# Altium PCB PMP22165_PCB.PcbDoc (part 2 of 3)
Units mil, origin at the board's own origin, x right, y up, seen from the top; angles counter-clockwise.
Board outline 3700 x 3000 mil, 4 copper layers (Top Layer, Signal Layer 1, Signal Layer 2, Bottom Layer), stack 61.634 mil thick; 232 components, 104 nets, 594 pads, 232 vias.
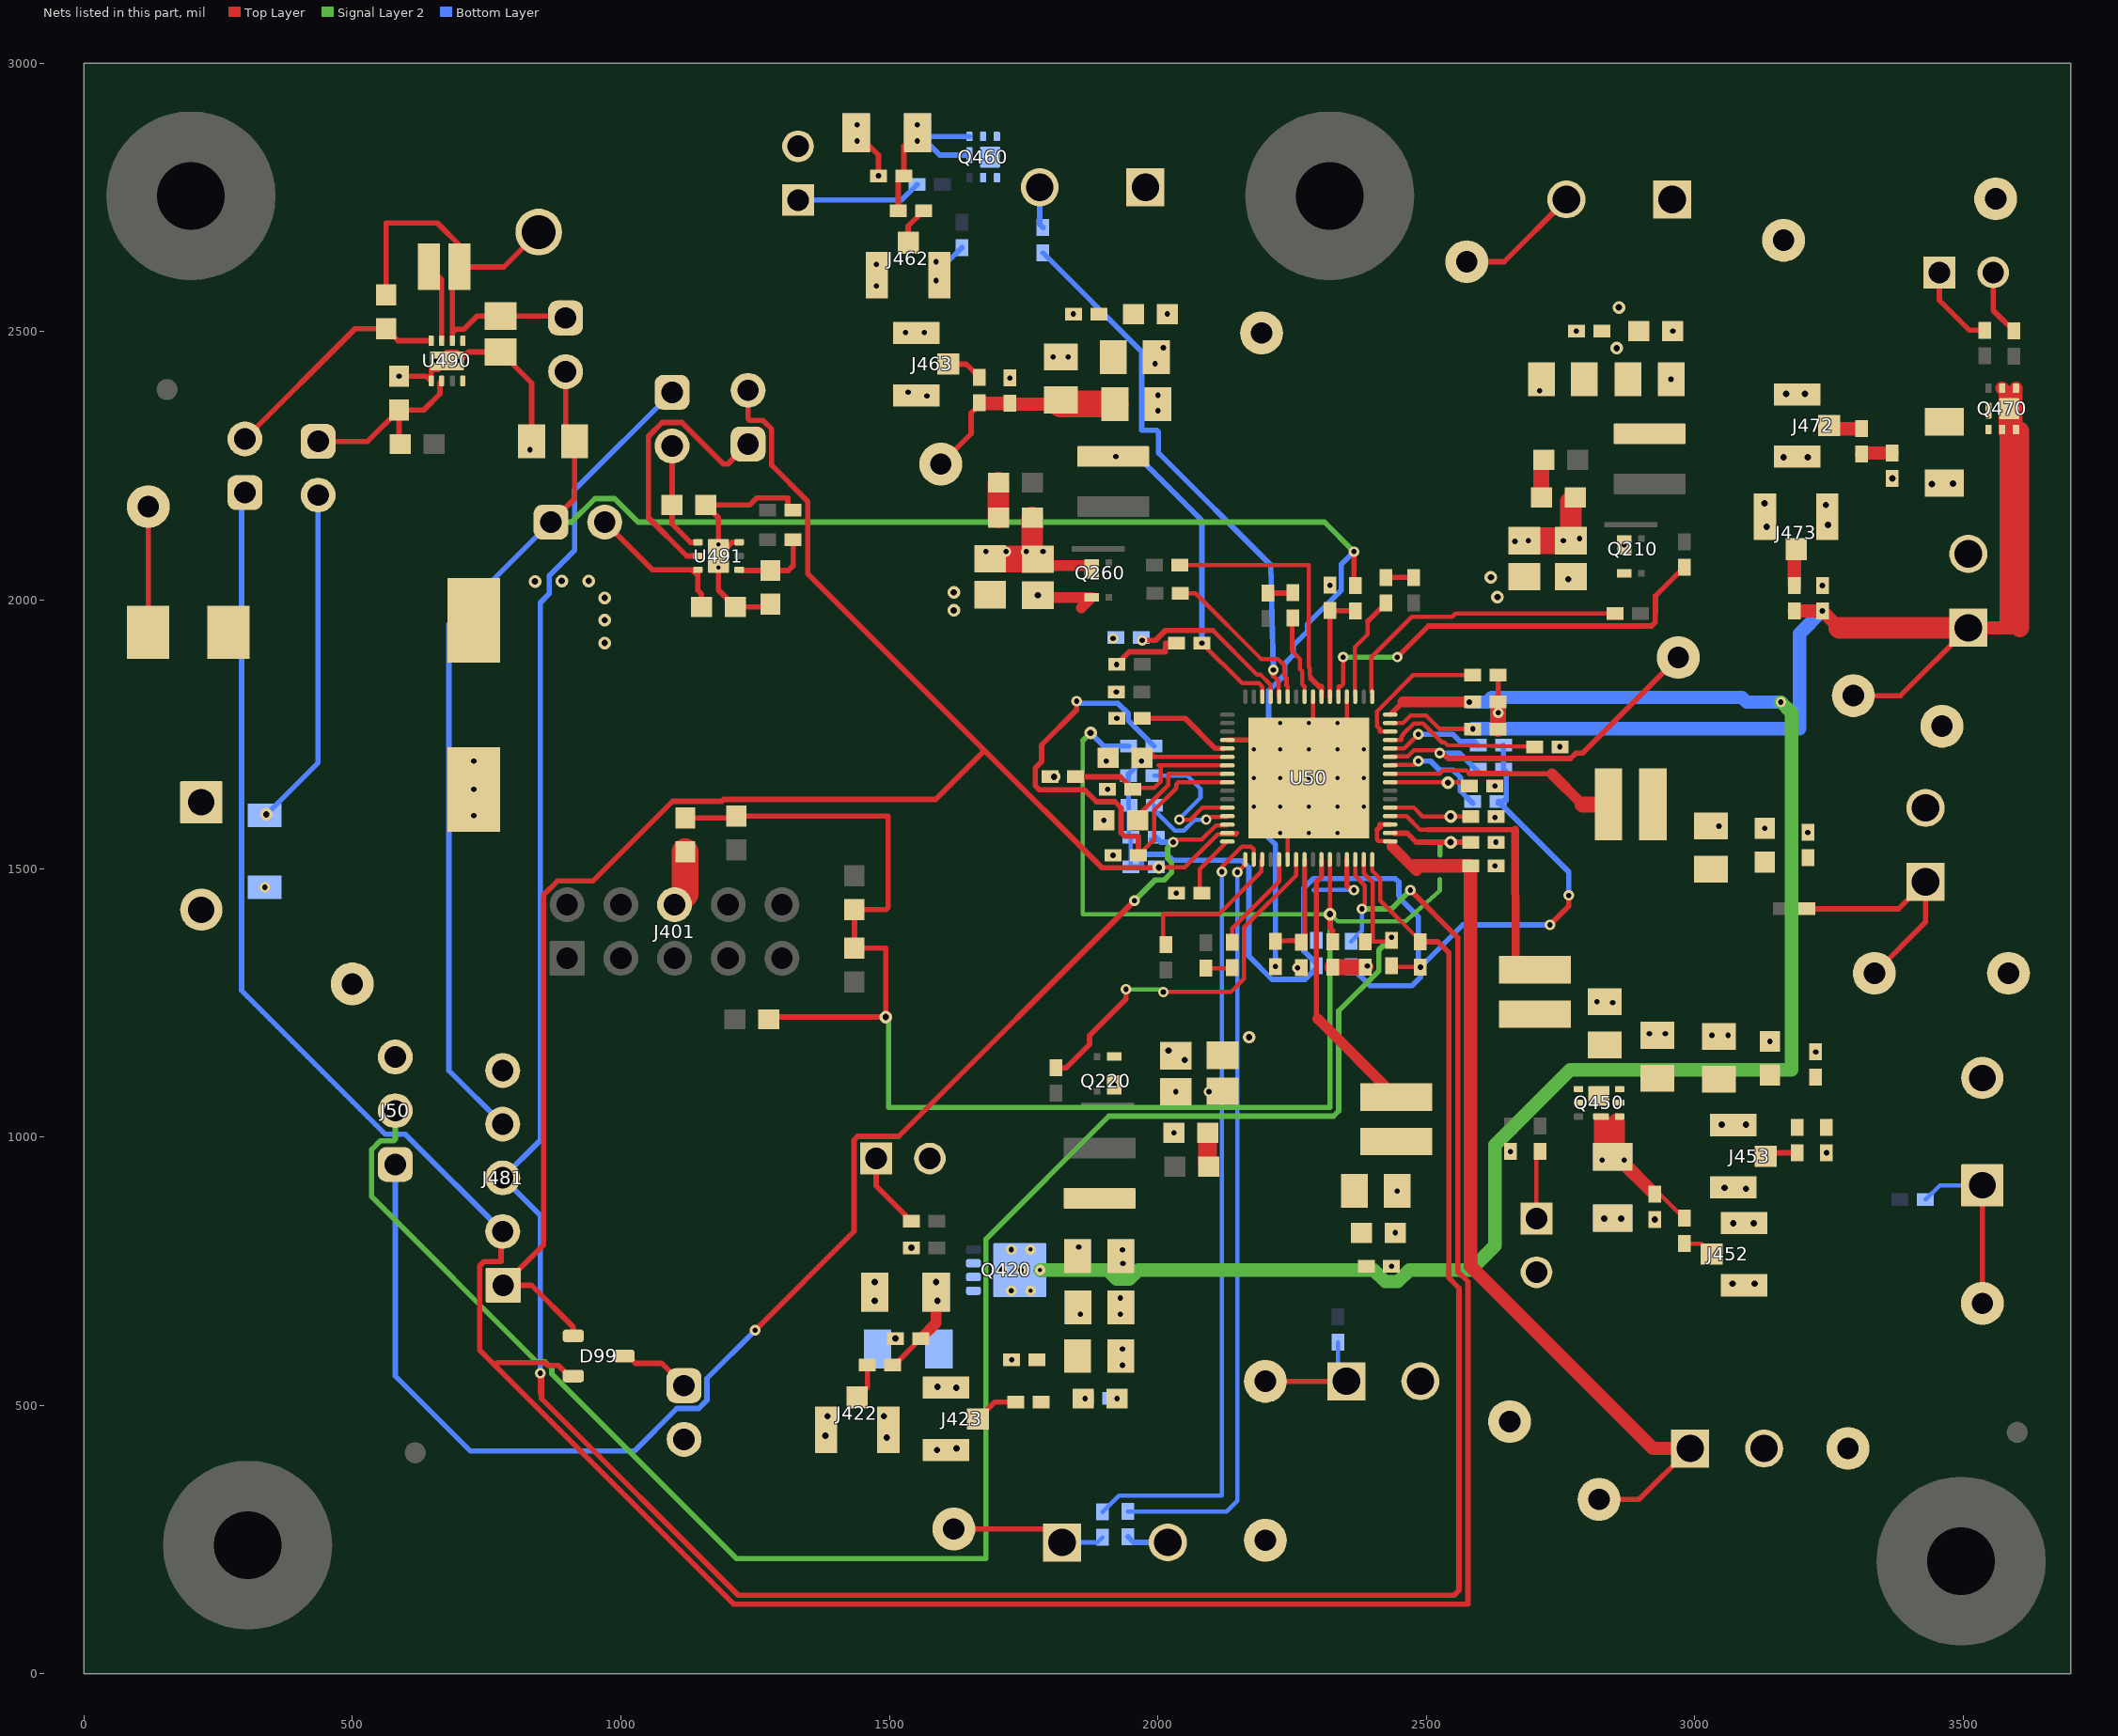
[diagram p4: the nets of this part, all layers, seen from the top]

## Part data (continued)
H5 H6 H7 H8: library part CMP-0003610-1, "Standoff, Hex, 0.5\"L #4-40 Nylon", Manufacturer=Keystone, Supplier Part Number 1=36-1902C-ND
J50: library part CMP-0075407-2, "Header, 100mil, 3x1, Gold, TH", Color=Black, Current_A=6.3A, Manufacturer=Samtec, Supplier Part Number 1=SAM1029-03-ND, Voltage_V=550V
J99 J491 J492 J493 J494 J495 J496: library part CMP-0075405-3, "Header, 100mil, 2x1, Gold, TH", Color=Black, Current_A=6.3A, Manufacturer=Samtec, Supplier Part Number 1=SAM1029-02-ND, Voltage_V=550V
J211 J221 J430 J440: library part CMP-0054825-2, "Terminal Block, 3.5mm, 2x1, Tin, TH", Color=Green, Current_A=10A, Manufacturer="Wurth Elektronik", Supplier Part Number 1=732-2747-ND, Voltage_V=300V
J400 J450: library part CMP-0074910-1, "Terminal Block, 5.08 mm, 2x1, Brass, TH", Color=Blue, Current_A=15A, Manufacturer="On-Shore Technology", Supplier Part Number 1=ED1609-ND, Voltage_V=300V
J401: library part CMP-0075410-2, "Header, 100mil, 5x2, Gold, TH", Color=Black, Current_A=6.3A, Manufacturer=Samtec, Supplier Part Number 1=SAM1028-05-ND, Voltage_V=550V
J410 J420 J460: library part CMP-0055506-1, "Terminal Block, 2x1, 5mm, Green, TH", Color=Green, Manufacturer="Phoenix Contact", PartNumber=1935776, Supplier Part Number 1=277-6405-ND
J421: library part CMP-0054947-1, "Header, 100mil, 2x1, Gold, TH", Manufacturer="TE Connectivity"
J422 J423 J452 J453 J462 J463 J472 J473: library part CMP-0075320-1, "Receptacle, Ultra Miniature Coaxial, Male Pin, 50 ohm, SMT", Color=Beige, Manufacturer="Hirose Electric Co. Ltd.", Supplier Part Number 1=H122041-ND
J451 J461 J471: library part CMP-0054947-1, "Header, 100mil, 2x1, Gold, TH", Manufacturer="TE Connectivity", PartNumber=5-146261-1
J481: library part CMP-0075411-1, "Header, 100mil, 5x1, Gold, TH", Color=Black, Current_A=6.3A, Manufacturer=Samtec, Supplier Part Number 1=SAM1029-05-ND, Voltage_V=550V
L210 L220 L260: library part CMP-0060983-2, "Inductor, Shielded, Composite, 1 µH, 8.75 A, 0.01 ohm, AEC-Q200 Grade 1, SMD", Manufacturer=Coilcraft, Value1="0.01 ohm", Value2=8.75A, ValueDisplayed=1uH
L230 L240 L250: library part CMP-0064156-1, "Inductor, Wirewound, 470 nH, 4.8 A, 0.018 ohm, SMD", Manufacturer="Wurth Elektronik", Supplier Part Number 1=732-5691-1-ND, Value1="0.018 ohm", Value2=4.8A, ValueDisplayed=470nH
L400: library part CMP-0059700-1, "Inductor, 55 nH, 30 A, 0.0002 ohm, SMD", Manufacturer="Delta Electronics Inc.", Value1="0.0002 ohm", Value2=30A, ValueDisplayed=55nH
L410: library part CMP-0061170-1, "Inductor, Shielded, Composite, 2.2 uH, 1.3 A, 0.16 ohm, SMD", Manufacturer=Coilcraft, Value1="0.16 ohm", Value2=1.3A, ValueDisplayed=2.2uH
LBL1: library part CMP-0003625-1, "Thermal Transfer Printable Labels, 0.650\" W x 0.200\" H - 10,000 per roll", Manufacturer=Brady, Supplier Part Number 1=97C5133
Logo1: library part CMP-0074838-1, "Texas Instrument Corporate Signature"
Logo2: library part CMP-0074844-1
Logo4: library part CMP-0074769-1
Q210 Q220 Q260: library part CMP-0066162-1, "Synchronous Buck NexFET Power Block II, MPC0005A (PTAB-5)", Alternate Manufacturer="Texas Instruments"
Q420: library part CMP-0000593-2, "MOSFET, N-CH, 30 V, 20 A, DNH0008A (VSONP-8)", Alternate Manufacturer=None, Manufacturer="Texas Instruments", PartNumber=CSD17579Q3A, Supplier Part Number 1=296-39998-1-ND, Value1=0.014, Value2="5.3 nC"
Q450 Q460 Q470: library part CMP-0000248-1, "MOSFET, N-CH, 25 V, 5 A, DQK0006C (WSON-6)", Alternate Manufacturer=None, Manufacturer="Texas Instruments", PartNumber=CSD16301Q2, Supplier Part Number 1=296-25260-1-ND, Value1=0.02, Value2="2 nC"
R50 R51 R52 R54 R55 R56 R210 R211 R212 R215 R220 R221 R222 R225 R226 R230 R240 R250 R260 R261 R262 R265: library part CMP-0026822-3, "RES, 0, 5%, 0.063 W, AEC-Q200 Grade 0, 0402", Manufacturer=Vishay-Dale, PartNumber=CRCW04020000Z0ED, Power_W=63mW, Supplier Part Number 1=541-0.0JCT-ND, TempCo="200 ppm/C", Tolerance_%=5%, Value2=0.063W, Value_Code=0000, ValueDisplayed=0
R57 R58 R59 R60 R61 R62 R63 R64 R65 R66 R67: library part CMP-0026823-3, "RES, 100 k, 5%, 0.063 W, AEC-Q200 Grade 0, 0402", Manufacturer=Vishay-Dale, PartNumber=CRCW0402100KJNED, Power_W=63mW, Supplier Part Number 1=541-100KJCT-ND, TempCo="200 ppm/C", Tolerance_%=5%, Value2=0.063W, Value_Code=100k
R213 R223 R263 R495: library part CMP-0025958-3, "RES, 10.0 k, 1%, 0.063 W, AEC-Q200 Grade 0, 0402", Manufacturer=Vishay-Dale, Power_W=63mW, Supplier Part Number 1=541-10.0KLCT-ND, TempCo="100 ppm/C", Tolerance_%=1%, Value2=0.063W, Value_Code=10k0, ValueDisplayed=10.0k
R214 R224 R264: library part CMP-0025834-4, "RES, 5.1, 5%, 0.1 W, AEC-Q200 Grade 0, 0603", Manufacturer=Vishay-Dale, PartNumber=CRCW06035R10JNEA, Power_W=100mW, Supplier Part Number 1=541-5.1GCT-ND, TempCo="200 ppm/C", Tolerance_%=5%, Value2=0.1W, Value_Code=5R10, ValueDisplayed=5.1
R401 R402 R403 R404: library part CMP-0025701-4, "RES, 10 k, 5%, 0.1 W, AEC-Q200 Grade 0, 0603", Manufacturer=Vishay-Dale, Power_W=100mW, Supplier Part Number 1=541-10KGCT-ND, TempCo="200 ppm/C", Tolerance_%=5%, Value2=0.1W, Value_Code=10k0, ValueDisplayed=10k
R421 R451 R461 R471: library part CMP-0026866-3, "RES, 1.0, 5%, 0.063 W, AEC-Q200 Grade 0, 0402", Manufacturer=Vishay-Dale, PartNumber=CRCW04021R00JNED, Power_W=63mW, Supplier Part Number 1=541-1.0JCT-ND, TempCo="200 ppm/C", Tolerance_%=5%, Value2=0.063W, Value_Code=1R00, ValueDisplayed=1.0
R422 R452 R462 R472: library part CMP-0025958-3, "RES, 10.0 k, 1%, 0.063 W, AEC-Q200 Grade 0, 0402", Manufacturer=Vishay-Dale, PartNumber=CRCW040210K0FKED, Power_W=63mW, Supplier Part Number 1=541-10.0KLCT-ND, TempCo="100 ppm/C", Tolerance_%=1%, Value2=0.063W, Value_Code=10k0, ValueDisplayed=10.0k
R423 R424 R429 R453 R454 R463 R464: library part CMP-0016745-3, "RES, 1.00, 1%, 0.25 W, AEC-Q200 Grade 0, 1206", Manufacturer=Vishay-Dale, PartNumber=CRCW12061R00FKEA, Power_W=250mW, Supplier Part Number 1=53K1855, TempCo="100 ppm/C", Tolerance_%=1%, Value2=0.25W, Value_Code=1R00, ValueDisplayed=1.00
R425 R426 R455 R456 R465 R466: library part CMP-0026404-2, "RES, 49.9, 1%, 0.063 W, AEC-Q200 Grade 0, 0402", Manufacturer=Vishay-Dale, PartNumber=CRCW040249R9FKED, Power_W=63mW, Supplier Part Number 1=541-49.9LCT-ND, TempCo="100 ppm/C", Tolerance_%=1%, Value2=0.063W, Value_Code=49R9, ValueDisplayed=49.9
R473: library part CMP-0016583-3, "RES, 10.0, 1%, 0.25 W, AEC-Q200 Grade 0, 1206", Manufacturer=Vishay-Dale, Power_W=250mW, Supplier Part Number 1=541-10.0FCT-ND, TempCo="100 ppm/C", Tolerance_%=1%, Value2=0.25W, Value_Code=10R0, ValueDisplayed=10.0
R475 R476: library part CMP-0026404-2, "RES, 49.9, 1%, 0.063 W, AEC-Q200 Grade 0, 0402", Manufacturer=Vishay-Dale, Power_W=63mW, Supplier Part Number 1=541-49.9LCT-ND, TempCo="100 ppm/C", Tolerance_%=1%, Value2=0.063W, Value_Code=49R9, ValueDisplayed=49.9
R490: library part CMP-0025697-4, "RES, 0, 5%, 0.1 W, AEC-Q200 Grade 0, 0603", Manufacturer=Vishay-Dale, Power_W=100mW, Supplier Part Number 1=541-0.0GCT-ND, TempCo="200 ppm/C", Tolerance_%=5%, Value2=0.1W, Value_Code=0000, ValueDisplayed=0
R491 R493: library part CMP-0021990-4, "RES, 100 k, 1%, 0.1 W, AEC-Q200 Grade 0, 0603", Manufacturer=Vishay-Dale, Power_W=100mW, Supplier Part Number 1=541-100KHCT-ND, TempCo="100 ppm/C", Tolerance_%=1%, Value2=0.1W, Value_Code=100k
R494: library part CMP-0026407-2, "RES, 4.22 k, 1%, 0.063 W, AEC-Q200 Grade 0, 0402", Manufacturer=Vishay-Dale, Power_W=63mW, Supplier Part Number 1=541-4.22KLCT-ND, TempCo="100 ppm/C", Tolerance_%=1%, Value2=0.063W, Value_Code=4k22, ValueDisplayed=4.22k
TP99: library part CMP-0055139-1, "Test Point, Miniature, White, TH", Color=White, Manufacturer=Keystone, Supplier Part Number 1=36-5002-ND
TP211 TP221 TP400 TP410 TP420 TP430 TP440 TP450 TP460: library part CMP-0055137-1, "Test Point, Miniature, Red, TH", Color=Red, Manufacturer=Keystone, Supplier Part Number 1=36-5000-ND
TP212 TP222 TP401 TP411 TP421 TP431 TP441 TP451 TP461: library part CMP-0055138-1, "Test Point, Miniature, Black, TH", Color=Black, Manufacturer=Keystone, Supplier Part Number 1=36-5001-ND
TP490: library part CMP-0055142-1, "Test Point, Compact, Red, TH", Color=Red, Manufacturer=Keystone, PartNumber=5005, Supplier Part Number 1=36-5005-ND
U50: library part CMP-0079628-1, "Configurable Multi-Rail PMIC for 2S & 3S Li-Ion Battery-Operated Devices or Non Battery Operated, RSK0064C (VQFN-64)", Alternate Manufacturer="Texas Instruments", Alternate PartNumber=TPS65086100RSKT
U490: library part CMP-0037799-2, "Buck Step Down Regulator with 3 to 17 V Input and 5 V Output, -40 to 85 degC, 8-Pin WSON (DSG), Green (RoHS & no Sb/Br)", Manufacturer="Texas Instruments", Rating=Catalog, Switch Current Limit(Typ)(A)=1.05
U491: library part CMP-0082614-1, "500-mA LDO With Power-Good, DRV0006A (WSON-6)", Alternate Manufacturer="Texas Instruments", Alternate PartNumber=TPS74501PDRVT, Operating Temperature Range="-40 to 125 C"
ZZ1: library part CMP-0003616-3
ZZ2: library part CMP-0077236-1
ZZ3: library part CMP-0077237-1
ZZ4: library part CMP-0077238-1

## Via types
v1: diameter 19.68, hole 10, Top Layer to Bottom Layer, 141 vias
v2: diameter 23.62, hole 11.81, Top Layer to Bottom Layer, 63 vias
v3: diameter 19.68, hole 7.87, Top Layer to Bottom Layer, 27 vias
v4: diameter 19.68, hole 7.87, Top Layer to Bottom Layer, tented both sides, 1 vias

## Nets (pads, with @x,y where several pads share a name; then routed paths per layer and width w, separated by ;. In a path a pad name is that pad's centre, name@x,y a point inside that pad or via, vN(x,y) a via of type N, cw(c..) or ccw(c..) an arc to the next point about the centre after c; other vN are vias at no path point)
0v78: C494.1 R494.2 U491.1 | length 152.9
  Top Layer w10: U491.1@1220.26,2056.44 1221.72,2054.99 C494.1@1278.54,2054.99 1311.79,2054.99 1320.86,2064.05 R494.2@1320.86,2112.03
0v78_Good: D99.1 J481.1 J496.2 R59.1 U50.63 | length 3345
  Top Layer w8: v2(2002,1502) 2050.27,1502 2111.53,1563.25 2144.52,1563.25 2144.9,1562.87 2148.1,1566.06 U50.63@2129.32,1566.06
  Top Layer w10: D99.1@911.41,629.57 911.41,646.38 833.86,723.92 J481.1@781,723.92 856.02,798.94 856.02,1450.89 881.78,1476.65 947.83,1476.65 1096.54,1625.35 1188.03,1625.35 1191.54,1628.85 1586,1628.85 1677.15,1720 ; J496.2@1236.87,2390.66 1236.87,2337.66 1239.89,2334.64 1264.6,2334.64 1280.85,2318.39 1280.85,2250.86 1348.11,2183.61 1348.11,2049.04 1677.15,1720 ; v2(2002,1502) 2001.28,1501.28 1895.87,1501.28 1677.15,1720
0v88: C250.1 C251.1 C252.1 C253.1 C254.1 C452.1 J450.1 L250.2 Q450.1 Q450.2 Q450.5 Q450.6 Q450.8 R250.2 R456.2 TP450.1 | length 337
  Top Layer w10: TP450.1@3535.16,690 J450.1@3535.16,910
  Bottom Layer w8: R250.2@3429.26,883.19 3456.07,910 J450.1@3535.16,910
1v1_IO: C230.1 C231.1 C232.1 J430.1 L230.2 R230.2 TP430.1 | length 230.6
  Top Layer w10: TP430.1@2200,545 J430.1@2351.1,545
  Bottom Layer w8: R230.2@2335,617.8 2335,561.1 J430.1@2351.1,545
1v2: C52.1 C263.1 C265.1 C266.1 C267.1 C268.1 C462.1 J460.2 L260.2 Q460.1 Q460.2 Q460.5 Q460.6 Q460.8 R265.2 R466.2 TP460.1 U50.46 | length 1088.3
  Top Layer w8: v1(2081.78,1920) 2156.5,1845.28 2187.78,1845.28 2194.28,1838.78 U50.46@2194.28,1820
  Top Layer w10: TP460.1@1595.83,2253.18 1652.22,2309.58 1652.22,2348.45 1667.57,2363.79 R466.2@1667.57,2367.73 R466.2@1668.95,2366.35
  Top Layer w25: R466.2@1668.95,2366.35 C462.1@1724.3,2366.35 ; C462.1@1724.3,2364.97 C266.1@1819.41,2364.97
  Top Layer w50: C266.1@1819.41,2364.97 C266.1@1819.41,2372.73 1827.16,2364.97 C263.1@1920,2364.97
  Bottom Layer w10: J460.2@1779.99,2768.63 1779.99,2699.64 R265.2@1786,2693.62 ; v1(1921.69,2267.31) 1962.69,2267.31 2081.78,2148.22 v1(2081.78,1920)
1v5: C56.1 C223.1 C225.1 C226.1 C227.1 C228.1 C229.1 C280.1 C422.1 J420.1 L220.2 Q420.5 Q420.6 Q420.7 Q420.8 Q420.9 R225.2 R426.2 TP420.1 U50.32 | length 3434
  Top Layer w8: v1(2580,1810) C56.1@2586.38,1810
  Top Layer w10: TP420.1@1620,270 1796.57,270 J420.1@1821.57,245 ; U50.32@2432.47,1786.54 2455.93,1810
  Top Layer w20: 2455.93,1810 v1(2580,1810)
  Signal Layer 2 w25: v4(1780.67,752.07) 1906.6,752.07 1923.05,735.62 1946.95,735.62 1963.4,752.07 2401.69,752.07 2423.14,730.62 2447.03,730.62 2468.48,752.07 2582.07,752.07 2627.77,797.77 2627.77,984.94 2767.7,1124.86 3179.86,1124.86 3179.86,1790.14 v1(3160,1810)
  Bottom Layer w8: J420.1@1821.57,245 1887.62,245 R225.2@1897,254.38
  Bottom Layer w10: v1(2580,1810) v1@2581.34,1811.34 ; v1@3158.66,1811.34 v1(3160,1810)
  Bottom Layer w25: v1(2580,1810) 2612.83,1810 2621.68,1818.84 3087.76,1818.84 3096.6,1810 v1(3160,1810)
  other v1: 1864.6,512.91 1855.77,670 1727.22,713.68 1709.41,752.07 1745.04,752.07 1727.22,790.45 1852.8,795
  other v3: 1762.85,713.68 1762.85,790.45
1v5_MGTAVAUX: C57.1 C472.1 J221.1 Q470.1 Q470.2 Q470.5 Q470.6 Q470.8 R476.2 TP221.1 U50.31 | length 2588
  Top Layer w8: U50.31@2432.47,1770.85 2456.58,1770.85 2470.57,1784.84 2499.43,1784.84 2524.27,1760 v1(2586.38,1760)
  Top Layer w10: TP221.1@3295,1821.97 3382.74,1821.97 J221.1@3509.1,1948.34
  Top Layer w25: R476.2@3185,1979.64 v1(3237.41,1979.64) 3268.71,1948.34 ; J221.1@3509.1,1948.34 3605,1948.34 ; Q470.2@3572.2,2394.58 3578.11,2388.67 3578.11,2330.85 3578.11,2310.1 3579.32,2308.9 3579.32,1963.41 ; Q470.6@3597.8,2322.06 Q470.1@3597.8,2394.58
  Top Layer w35: 3605,1948.34 3605,2314.85
  Top Layer w40: 3268.71,1948.34 J221.1@3509.1,1948.34
  Bottom Layer w25: v1@2586.38,1760.35 3195,1760.35 3195,1937.23 v1(3237.41,1979.64)
2v5_IO: C240.1 C241.1 C242.1 J440.1 L240.2 R240.2 TP440.1 | length 450.7
  Top Layer w10: R240.2@3208.62,1425 3379.26,1425 J440.1@3429.26,1475 3429.26,1400.1 TP440.1@3334.16,1305
3v3: C53.1 C54.1 C55.1 C63.1 C213.1 C215.1 C216.1 C217.1 C401.1 J410.2 L210.2 R56.2 R215.2 R401.2 R402.2 R403.2 R404.2 TP410.1 U50.11 U50.18 U50.21 U50.24 | length 4452.9
  Top Layer w8: v2(2320.26,1415) U50.11@2320.26,1516.85 ; U50.21@2432.47,1613.31 2476.69,1613.31 2492.91,1597.09 C55.1@2582.32,1597.09 ; U50.24@2432.47,1660.55 C54.1@2573.06,1660.55
  Top Layer w10: C401.1@1120,1594.16 1211.5,1594.16 R402.2@1215,1597.67 1497.67,1597.67 1497.67,1427.33 1493.84,1423.5 R403.2@1435,1423.5 R404.2@1435,1351.5 1493.5,1351.5 v2(1493.5,1223.5) 1279.48,1223.5 R401.2@1275.02,1219.05 ; v2(2320.26,1415) 2320.26,1389.44 2325.33,1384.37 C53.1@2325.33,1363.62 ; U50.18@2439.95,1566.06 2440.26,1565.75 2464.43,1565.75 2481.17,1549.02 v2(2545,1549.02) C63.1@2582.32,1549.02 ; C54.1@2573.06,1660.55 C54.1@2580.16,1653.46 ; TP410.1@2575,2630 2644.55,2630 J410.2@2760.66,2746.11
  Signal Layer 2 w8: 1860,1738.03 1860,1415 v2(2320.26,1415) 2335,1401.34 2461.34,1401.34 2465,1405 2524.75,1458.26 2524.75,1480.61
  Signal Layer 2 w10: v2(1493.5,1223.5) 1498.77,1218.24 1498.77,1055.26 2320.26,1055.26 v2(2320.26,1415) ; 1860,1738.03 v2(1874.57,1752.6) ; 2525,1525 2525,1549.02
  Bottom Layer w10: v2(1874.57,1752.6) 1899.22,1727.94 R56.2@1945.46,1727.94
  other v1: 2748.48,1726.76
  other v2: 2545,1597.09 2540,1660 2854.38,2469.03 2858.43,2545
3v3-IO: C64.1 J211.1 TP211.1 U50.17 U50.19 | length 1748.3
  Top Layer w8: 2408.19,1572.04 2408.19,1553.53 2410.09,1551.63 2432.47,1551.63 U50.17@2432.47,1550.31
  Top Layer w10: 2408.19,1572.04 2413.69,1577.54 2413.69,1581.81 U50.19@2432.47,1581.81 ; TP211.1@2821.43,325 2896.1,325 J211.1@2991.1,420
  Top Layer w20: 2435.85,1541.09 2481.17,1495.78
  Top Layer w25: 2477.78,1505 C64.1@2582.32,1505 2582.32,759.49 2921.81,420 J211.1@2991.1,420
3v3_Good: J481.3 J495.1 R65.2 U50.16 | length 5382.4
  Top Layer w8: U50.16@2399,1516.85 2399,1495.78 2414.34,1480.44 2414.34,1439.93 2488.9,1365.38 R65.2@2488.9,1363.62
  Top Layer w10: 850,523.33 v1(850,560) 852.09,557.91 852.09,512.91 1218.5,146.5 2551.5,146.5 2560.82,155.82 2560.82,718.68 2541.82,737.68 2541.82,1343.18 2521.38,1363.62 R65.2@2488.9,1363.62
  Bottom Layer w10: v1(850,560) 850,853.92 J481.3@780,923.92 850,993.92 850,1995.14 866.69,2011.82 866.69,2045.19 913.98,2092.48 913.98,2205.33 J495.1@1095.38,2386.72
3v3_SU: C61.1 R57.2 R58.2 R59.2 R60.2 R61.2 R62.2 R63.1 R64.1 R65.1 R66.1 R67.1 U50.54 | length 2353.3
  Top Layer w8: 1992.6,1707.8 U50.54@2129.32,1707.8 ; R67.1@2435.26,1318.82 2437.7,1316.38 v1(2488.9,1316.38)
  Top Layer w10: C61.1@1989.35,1711.05 1992.6,1707.8 ; v1(2730,1395) 2765,1430 v1(2765,1450)
  Bottom Layer w8: R62.2@1945.46,1672.94 1945.46,1618.43 R60.2@1945.94,1617.94 1945.94,1561.39 R58.2@1949.4,1557.94 R59.2@1949.4,1502.94
  Bottom Layer w10: R62.2@1945.46,1672.94 1945.46,1676.07 v1(1969.39,1700) ; R59.2@1949.4,1502.94 1969.39,1502.94 1969.39,1526.25 2017.15,1526.25 2028.06,1515.34 2127.84,1515.34 2128.84,1514.34 2156.84,1514.34 2169.34,1501.84 2169.34,1336.85 2212.54,1293.66 2274.04,1293.66 2295.26,1314.88 R57.2@2295.26,1318.82 2295.26,1322.76 2272.47,1345.55 2271.95,1345.55 2271.95,1463.87 2289.42,1481.34 2441.89,1481.34 2448.66,1474.58 2448.66,1449.82 2450,1448.47 2450,1445 2485,1410 2485,1320.28 v1(2488.9,1316.38) ; R61.2@2359.94,1316.85 2395,1281.79 2473.21,1281.79 2488.9,1297.48 v1(2488.9,1316.38) ; R64.1@2633.62,1625 2635.54,1623.09 2765,1493.62 v1(2765,1450) ; R64.1@2633.7,1621.25 R64.1@2637.45,1625 ; R64.1@2643.62,1626.38 2648.74,1626.38 2648.74,1679.88 R66.1@2643.62,1685 R63.1@2643.62,1729.54 ; v1(2730,1395) 2567.52,1395 v1(2488.9,1316.38)
5v: C412.1 J481.4 J493.2 J494.1 R50.1 R51.1 | length 4009
  Top Layer w10: J494.1@870,2145 913.91,2188.91 C412.1@913.91,2295.44 897.17,2312.17 J493.2@897.17,2425.44 ; v1(2365,2090.2) 2365,2029.39 R50.1@2367.51,2026.88
  Signal Layer 2 w10: J494.1@870,2145 907.8,2145 951.78,2188.98 988.22,2188.98 1032.2,2145 2310.2,2145 v1(2365,2090.2)
  Bottom Layer w10: J481.4@780,1023.92 680,1123.92 680,1955 J494.1@870,2145 ; v1(2219,1317.38) 2219,1544.51 2206.36,1557.14 2206.36,1831.18 2236.34,1861.16 2236.34,1880.37 2239.23,1883.26 2239.23,1884.91 2251.92,1897.6 2251.92,1915.09 2278.25,1941.43 2278.25,1955.25 2341.61,2018.6 2341.61,2066.81 v1(2365,2090.2)
5v_Good: D99.2 J481.2 J492.1 R61.1 U50.14 | length 5703.7
  Top Layer w8: U50.14@2367.51,1516.85 2367.51,1486.26 2385.34,1468.43 2385.34,1430.34 v1(2380,1425)
  Top Layer w10: J481.2@780,823.92 776.99,820.91 776.99,767.9 744.9,767.9 737.02,760.03 737.02,602.98 765.35,574.65 ; D99.2@911.41,554.76 903.53,554.76 883.64,574.65 863.41,574.65 858.22,579.84 770.54,579.84 765.35,574.65 ; v1(2470,1460) 2558.32,1371.68 2558.32,749.55 2577.32,730.55 2577.32,130 1210,130 765.35,574.65
  Signal Layer 2 w10: v1(2380,1425) 2435,1425 v1(2470,1460)
  Bottom Layer w8: R61.1@2359.94,1364.09 2380,1384.15 v1(2380,1425)
  Bottom Layer w10: J492.1@300,2200 293.96,2193.96 293.96,1272.73 561.78,1004.91 599.01,1004.91 J481.2@780,823.92
12V: C402.2 J400.1 J491.2 L400.1 TP400.1 | length 868.7
  Top Layer w10: L400.1@119.49,1940 120,1940.51 TP400.1@120,2174.01
  Bottom Layer w10: v2(340,1600.83) 436.25,1697.08 J491.2@436.25,2195.44
12V_B: C210.1 C211.1 C220.1 C221.1 C260.1 C261.1 C403.1 L400.2 Q210.2 Q220.2 Q260.2 R55.2 | length 132.8
  Top Layer w10: v2(1776.48,2009.14) C260.1@1780.69,2004.93 ; 1857.44,1982.01 1857.44,1985.69
  Top Layer w20: C260.1@1780.69,2004.93 Q260.2@1876.68,2004.93 1857.44,1985.69
  other v2: 2050,1143.25 2020,1160.96 2170,1185.89 1806.62,1670.83 970,1920 970,1962.47 1620,1980.79 970,2004.14 2632.32,2005.52 1620,2014.3 840,2034.79 890,2035.53 940,2035.53 2764.18,2038.81 2620,2042.08
BOOT1: R210.1 U50.35 | length 199
  Top Layer w8: U50.35@2367.51,1820 2366.76,1820.75 2366.76,1912.29 2390.82,1936.35 2390.82,1960.41
  Top Layer w10: 2390.82,1960.41 R210.1@2425,1994.6
BOOT2: R220.1 U50.5 | length 190.7
  Top Layer w8: R220.1@2138.2,1362.41 2138.2,1388.4 2225.78,1475.98 U50.5@2225.78,1516.85
BOOT6: R260.1 U50.41 | length 151.6
  Top Layer w8: R260.1@2250.01,1962.03 2250.01,1904.77 2264.34,1890.44 2264.34,1871.22 2268.47,1867.1 2268.47,1853.09 2269.02,1852.54 2269.02,1842.78 2273.02,1838.78 U50.41@2273.02,1820
CTL1: R57.1 U50.13 | length 238.2
  Top Layer w8: v1@2362.62,1457.62 v1(2365,1460)
  Top Layer w10: U50.13@2351.76,1516.85 2351.76,1468.48 v1@2362.62,1457.62
  Bottom Layer w8: R57.1@2295.26,1366.06 2295.26,1454.74 2290,1460 v1(2365,1460)
CTL2: R62.1 U50.60 | length 268.5
  Top Layer w8: v1(2039.97,1591) 2060.45,1591 2082.75,1613.31 U50.60@2129.32,1613.31
  Bottom Layer w8: R62.1@1993.34,1673 2054.77,1673 2079.34,1648.43 2079.34,1631.57 2039.97,1592.2 v1(2039.97,1591)
CTL3/SLPENB1: R60.1 U50.61 | length 172.1
  Top Layer w8: v1(2090,1591) 2095.25,1596.25 2128.01,1596.25 U50.61@2129.32,1597.56
  Bottom Layer w8: R60.1@1993.19,1617.94 1993.19,1609.01 2031.54,1570.66 2048.39,1570.66 2068.74,1591 v1(2090,1591)
CTL4: J50.1 R58.1 U50.62 | length 2695.9
  Top Layer w8: v1(2028.43,1548.98) 2033.44,1554 2081.77,1554 2108.27,1580.5 2128.07,1580.5 U50.62@2129.32,1581.75
  Top Layer w10: v1(1250,640) 1434.25,824.25 1434.25,994.29 1440.98,1001.03 1517.24,1001.03 v1(1956.21,1440)
  Signal Layer 2 w10: v1(1956.21,1440) 1994.9,1478.69 2011.66,1478.69 2025.31,1492.34 2025.31,1511.66 2018,1518.97 2018,1538.56 v1(2028.43,1548.98)
  Bottom Layer w10: J50.1@580,948.89 580,555 720,415 1025,415 1104.43,494.43 1144.85,494.43 1160.22,509.81 1160.22,550.22 v1(1250,640) ; R58.1@1988.07,1551.32 1988.07,1554 R58.1@2000.58,1554 ; R58.1@1996.64,1557.94 R58.1@2000.58,1554 ; v1(2028.43,1548.98) 2005.6,1548.98 R58.1@2000.58,1554
DRVH1: R211.1 U50.33 | length 552.2
  Top Layer w8: U50.33@2397.76,1828.86 2397.76,1893.75 2472.76,1968.75 2547.76,1968.75 2554,1975 R211.1@2851.38,1975
DRVH2: R221.1 U50.3 | length 297.3
  Top Layer w8: R221.1@2015,1358.62 2010,1363.62 2010,1415 2113.5,1415 2192.97,1494.47 2192.97,1515.54 U50.3@2194.28,1516.85
DRVH6: R261.1 U50.43 | length 310.3
  Top Layer w8: R261.1@2041.62,2012.6 2070,2012.6 2192.26,1890.34 2223.43,1890.34 2235.34,1878.43 2235.34,1859.21 2239.47,1855.08 2239.47,1841.08 2241.52,1839.02 U50.43@2241.52,1820
DRVL1: R212.1 U50.37 | length 812.8
  Top Layer w8: U50.37@2336.01,1820 2336.01,1838.78 2340.28,1838.78 2345,1843.5 v1(2345,1893.75)
  Top Layer w10: v1(2445.83,1893.75) 2503.77,1951.69 2919.13,1951.69 2925.87,1958.43 2925.87,1976.21 2926.44,1976.79 2926.44,2007.65 R212.1@2980,2061.21
  Signal Layer 2 w10: v1(2345,1893.75) v1(2445.83,1893.75)
DRVL2: R222.1 U50.7 | length 709.9
  Top Layer w8: v1(2010,1270) 2135.44,1270 2160.51,1295.07 2160.51,1390.21 2257.27,1486.97 U50.7@2257.27,1516.85
  Top Layer w10: R222.1@1810,1132.56 R222.1@1810,1128.62 1829.12,1128.62 1872.8,1172.3 1872.8,1188.98 1940.46,1256.63 v1(1940.46,1275)
  Signal Layer 2 w8: v1(1940.46,1275) 2005,1275 v1(2010,1270)
DRVL6: R262.1 U50.39 | length 497.1
  Top Layer w8: R262.1@2041.11,2065 2280.91,2065 2280.91,1875.16 2282.97,1873.1 2282.97,1859.1 2285.02,1857.04 2285.02,1854
  Top Layer w10: 2285.02,1854 2300.25,1838.78 2304.52,1838.78 U50.39@2304.52,1820
FBGND2: R226.1 U50.1 | length 1412.2
  Top Layer w8: v1(2148,1493) 2162.78,1507.78 U50.1@2162.78,1516.85
  Bottom Layer w8: R226.1@1944.4,302.62 2128,302.62 2147.69,322.31 2147.69,1492.69 v1(2148,1493)
FBVOUT1: R215.1 U50.29 | length 303.2
  Top Layer w8: U50.29@2432.47,1739.29 2453.54,1739.29 2453.79,1739.54 2453.79,1746.1 2456.75,1749.06 2456.75,1750.52 2476.57,1770.34 2493.43,1770.34 2528.43,1735.34 2533.17,1735.34 2538.98,1729.54 R215.1@2701.23,1726.76
FBVOUT2: R225.1 U50.2 | length 1502.2
  Top Layer w8: v1(2119,1494) 2119,1503.33 2156.8,1541.13 2173.03,1541.13 2178.53,1535.63 U50.2@2178.53,1516.85
  Bottom Layer w8: R225.1@1897,301.62 1927.38,332 2119,332 v1(2119,1494)
FBVOUT6: R265.1 U50.44 | length 1022.9
  Top Layer w8: 2215,1859.05 2224.97,1849.08 2224.97,1820.81 U50.44@2225.78,1820
  Top Layer w10: 2215,1859.05 v1(2215,1870)
  Bottom Layer w10: R265.1@1786,2646.38 1970,2462.38 1970,2316.38 1997.97,2316.38 2001.19,2313.15 2001.19,2273.81 2210,2065 v1(2215,1870)
GND: C50.2 C51.2 C52.2 C53.2 C54.2 C55.2 C56.2 C57.2 C58.2 C59.2 C60.2 C61.2 C62.2 C63.2 C64.2 C65.2 C210.2 C211.2 C213.2 C214.2 C215.2 C216.2 C217.2 C220.2 C221.2 C223.2 C224.2 C225.2 C226.2 C227.2 C228.2 C229.2 C230.2 C231.2 C232.2 C240.2 C241.2 C242.2 C250.2 C251.2 C252.2 C253.2 C254.2 C260.2 C261.2 C263.2 C264.2 C265.2 C266.2 C267.2 C268.2 C280.2 C401.2 C402.1 C403.2 C412.2 C421.2 C422.2 C451.2 C452.2 C461.2 C462.2 C471.2 C472.2 C490.2 C491.2 C493.2 C494.2 J50.3 J99.2 J211.2 J221.2 J400.2 J401.6 J410.1 J420.2 J421.2 J422.2@1498.07,455 J422.3@1381.93,455 J423.2@1605,416.93 J423.3@1605,533.07 J430.2 J440.2 J450.2 J451.2 J452.2@3091.43,839.97 J452.3@3091.43,723.83 J453.2@3071.57,906.17 J453.3@3071.57,1022.32 J460.1 J461.2 J462.2@1593.07,2605.44 J462.3@1476.93,2605.44 J463.2@1550,2381.28 J463.3@1550,2497.42 J471.2 J472.2@3190.15,2266.93 J472.3@3190.15,2383.07 J473.2@3130.43,2155.03 J473.3@3246.57,2155.03 J481.5 Q210.3 Q220.3 Q260.3 R52.2 R54.2 R213.2 R223.2 R226.2 R263.2 R422.1 R423.1 R424.1 R429.1 R452.1 R453.1 R454.1 R462.1 R463.1 R464.1 R472.1 R473.1 R493.1 R495.1 TP212.1 TP222.1 TP401.1 TP411.1 TP421.1 TP431.1 TP441.1 TP451.1 TP461.1 U50.6 U50.36 U50.40 U50.52 U50.65 U490.1 U490.4 U490.5 U490.9@676.3,2445.48 U491.3 U491.7@1181.87,2082.03 | length 2523.4
  Top Layer w8: U50.6@2242,1522.15 U50.65@2242,1567.52 ; U50.65@2289.04,1779.59 U50.40@2289.04,1813.91 ; 2351.76,1781.65 U50.36@2351.76,1815.97
  Top Layer w10: v1(587.11,2416.93) 637.91,2416.93 U490.1@646.77,2408.07 646.77,2429.42 660.24,2429.42 U490.9@676.3,2445.48 ; U490.9@694.67,2461.54 676.3,2461.54 U490.9@676.3,2445.48 ; U490.5@705.83,2479.23 U490.5@705.83,2482.88 ; C412.2@833.91,2295.44 833.91,2404.21 C491.2@776.14,2461.97 716.06,2461.97 689.09,2435 678.61,2445.48 U490.9@676.3,2445.48 ; 1207.46,2107.63 U491.7@1181.87,2082.03 ; C494.2@1278.54,1992 1273.58,1987.03 C493.2@1213.37,1987.03 1181.87,2018.53 v3(1181.87,2060.38) U491.7@1181.87,2082.03 ; R495.1@1320.86,2167.03 1310.86,2177.03 1310.86,2190.35 1253.11,2190.35 1239.79,2177.03 R493.1@1158.37,2177.03 1181.87,2153.53 v3(1181.87,2103.69) U491.7@1181.87,2082.03 ; R464.1@1438.03,2870.56 1479.88,2828.71 v1(1479.88,2790) ; C260.2@1765,2076.8 C260.2@1766.18,2077.98 ; C260.2@1776.48,2076.07 C260.2@1794.85,2057.7 ; v1(1923.14,1880) 1946.8,1903.66 2014.05,1903.66 2014.05,1920 C52.2@2034.53,1920 ; U50.52@2129.32,1739.29 U50.65@2210.03,1739.29 ; C56.2@2633.62,1810 R213.2@2633.62,1860 ; J471.2@3555.33,2610 3555.33,2539.53 R472.1@3593.75,2501.11
  Top Layer w20: C260.2@1789.8,2064.32 Q260.3@1871.57,2064.32
  Top Layer w30: C53.2@2325.33,1316.38 C65.2@2386.46,1316.38 ; C57.2@2633.62,1760 C56.2@2633.62,1810
  Top Layer w40: C260.2@1766.18,2077.98 C264.2@1766.18,2153.63 ; C210.2@2769.18,2110.74 C214.2@2769.18,2183.32
  Top Layer w50: J401.6@1100,1432.67 1120,1452.67 C401.2@1120,1531.17 ; C261.2@1687.64,2076.8 C260.2@1765,2076.8 ; U50.65@2210.03,1739.29 v3(2227.7,1721.61) v3(2280.89,1668.43) ; C211.2@2682.48,2110.74 C210.2@2769.18,2110.74
  Bottom Layer w10: v1(1475.94,2585) v1(1475.94,2625) ; v1(1587.09,2595) v1(1587.09,2630) 1608.62,2630 R462.1@1635,2656.38 ; R226.2@1944.4,255.38 1954.78,245 J420.2@2018.43,245
  other v1: 1924.15,512.91 1934.07,575 1727.76,585 1934.07,605 1930,670 1930,700 2435.08,759.46 1935,764.46 1934.07,790 2441.89,821.62 2445.83,899.46 3245,970.62 2656.61,972.99 2029.85,1007.66 2033.43,1084.19 2095,1084.19 1918.87,1096.81 3224.85,1158.33 3139.85,1178.01 3031.39,1189.34 3061.66,1189.34 2915,1192.65 2945,1192.65 2846.94,1250 2817.51,1251.77 2260,1315 2390,1318.35 2034.38,1454 336.96,1465 2627.6,1505 1916.38,1524.59 2629.57,1549.02 3210.16,1567.15 3130.16,1575.02 3044.85,1578.96 1899.58,1590 2627.6,1595 726.14,1598.31 726.14,1647.52 1906.38,1647.52 2627.4,1653.46 726.14,1700 1904.06,1700 1923.56,1779.59 2633.62,1790 1922.51,1828.86 1916.36,1928.52 2320.26,2027.44 3237.41,2026.88 1680,2090.2 1717.16,2090.2 1755,2090.2 1786,2090.2 2868.22,2102.75 2665,2109.31 2690,2110.74 2755,2110.74 2785,2114.4 830.6,2280 2000,2352.45 1570,2380.3 2000,2381.28 1535,2387.26 2710.68,2390 2955.48,2411.11 1724.3,2413.6 1995,2440 1805,2452.73 1832.7,2452.73 2010,2470 1530,2498.41 1565,2498.41 2779.24,2501.11 2958.74,2501.11 1842.6,2532.73 2017.49,2532.73 1440,2855 1440,2885
  other v2: 1588.62,416.93 1625.28,419.88 1495.12,440 1380.94,443.5 1384.88,480 1490,480 1624.49,533.07 1589.7,534.68 1511.38,624.69 1472.91,695 3070,726.78 3111.15,726.78 1472.91,730 1541.08,793.73 3071.57,839.24 3109.43,839.24 2925,846.38 2831.19,848.1 2862.69,848.1 3095,903.69 3055,905.19 3050,1023.3 3095,1023.3 3133.39,2136.38 3247.56,2140 3243.62,2177.03 3129.45,2180 3441.07,2215.94 3480.44,2216.93 3367.59,2226.38 3165,2265.95 3210,2265.95 3170,2384.06 3205,2384.06
  other v3: 2227.7,1565.98 2280.89,1565.98 2334.08,1565.98 2178.45,1615.24 2227.7,1615.24 2280.89,1615.24 2334.08,1615.24 2383.33,1615.24 2178.45,1668.43 2227.7,1668.43 2334.08,1668.43 2383.33,1668.43 2178.45,1721.61 2280.89,1721.61 2334.08,1721.61 2383.33,1721.61 2227.7,1770.87 2280.89,1770.87 2334.08,1770.87 654.65,2445.48 697.95,2445.48
GPO2: R64.2 U50.26 | length 204.7
  Top Layer w8: U50.26@2432.47,1692.05 2433.78,1693.36 2478.36,1693.36 v1(2485,1700)
  Bottom Layer w10: v1(2485,1700) 2507.71,1700 2524.4,1683.31 2549.66,1683.31 2563.31,1669.66 2563.31,1644.4 R64.2@2586.46,1621.25
GPO3: R66.2 TP99.1 U50.27 | length 712
  Top Layer w8: U50.27@2432.47,1707.86 2433.72,1709.11 2465.34,1709.11 2476.57,1720.34 2519.4,1720.34 v1(2524.75,1715)
  Top Layer w10: v1(2524.75,1715) 2530,1715 2540.05,1704.94 2768.37,1704.94 2778.42,1715 2791.05,1715 TP99.1@2968.97,1892.92
  Bottom Layer w10: v1(2524.75,1715) 2561.38,1715 R66.2@2596.38,1680
GPO4: R63.2 U50.28 | length 183.3
  Top Layer w8: U50.28@2432.47,1723.61 2458.61,1723.61 v1(2485,1750)
  Bottom Layer w10: v1(2485,1750) 2549.14,1750 2562.79,1736.35 2589.57,1736.35 R63.2@2596.38,1729.54
ILIM1: R213.1 U50.30 | length 264.7
  Top Layer w8: U50.30@2432.47,1755.04 2413.69,1755.04 2413.69,1759.31 2408.19,1764.81 2408.19,1792.52 2475.67,1860 R213.1@2586.38,1860
ILIM2: R223.1 U50.64 | length 119
  Top Layer w8: R223.1@2081.62,1454 2078,1457.62 2078,1499 U50.64@2129.32,1550.31 U50.64@2129.32,1550.31
ILIM6: R263.1 U50.45 | length 310.8
  Top Layer w8: 2102.29,1943.31 2184.82,1860.78 2191.35,1860.78 2210.03,1842.1 U50.45@2210.03,1820
  Top Layer w10: v1(1970.83,1925) 1995.71,1925 2014.02,1943.31 2102.29,1943.31
IRQB: C65.1 J50.2 R67.2 U50.15 | length 3548
  Top Layer w8: C65.1@2383.26,1366.83 C65.1@2386.46,1363.62 2432.82,1363.62 R67.2@2435.26,1366.06 ; U50.15@2383.26,1516.85 2383.26,1491.02 2399.84,1474.43 2399.84,1433.93 2400.34,1433.43 2400.34,1366.83
  Signal Layer 2 w10: J50.2@580,1048.89 580,995.89 576.99,992.87 552.27,992.87 536.02,976.62 536.02,888.82 843.5,581.34 858.84,581.34 871.34,568.84 871.34,558.66 1215,215 1680,215 1680,810 1908.76,1038.76 2327.1,1038.76 2336.76,1048.43 2336.76,1234.93 2411.34,1309.51 2411.34,1348.21 v1(2435.08,1371.95)
NetC50_1: C50.1 R51.2 U50.8 | length 205.9
  Top Layer w10: R51.2@2219,1364.62 2263.43,1366.06 C50.1@2266.78,1362.72 2273.02,1368.96 U50.8@2273.02,1516.85
NetC51_1: C51.1 R50.2 U50.38 | length 207.7
  Top Layer w10: U50.38@2320.26,1820 C51.1@2320.26,1980.2 2366.95,1980.2 R50.2@2367.51,1979.64
NetC58_1: C58.1 R55.1 U50.55 | length 334.2
  Top Layer w8: C58.1@1953.62,1647.52 1956.03,1649.93 1993.28,1649.93 2005,1661.64 2005,1688.48 2001.43,1692.05 U50.55@2129.32,1692.05
  Top Layer w10: R55.1@1846.09,1670.86 1930.28,1670.86 C58.1@1953.62,1647.52
NetC59_1: C59.1 U50.53 | length 174.5
  Top Layer w10: C59.1@1970.8,1779.59 2050.79,1779.59 2106.53,1723.85 2121.42,1723.85 U50.53@2121.98,1723.3
NetC60_1: C60.1 U50.56 | length 219.5
  Top Layer w8: C60.1@1962.58,1590 1962.58,1598.71 2019.5,1655.64 2019.5,1676 2019.8,1676.3 U50.56@2129.32,1676.3
NetC62_1: C62.1 R56.1 U50.57 | length 928.4
  Top Layer w8: C62.1@1963.62,1524.59 1990.03,1551 1993,1551 1993,1608.63 2034,1649.63 2034,1656.46 2038.09,1660.55 U50.57@2129.32,1660.55
  Top Layer w10: v1(1848.53,1811.6) 1848.53,1795.42 1783.31,1730.2 1783.31,1699.15 1771.6,1687.44 1771.6,1654.29 1779.19,1646.69 1863.39,1646.69 1885.87,1624.21 1920.03,1624.21 1931.39,1612.84 1931.39,1566.54 1938.13,1559.8 1963.05,1559.8 1963.62,1559.22 C62.1@1963.62,1524.59
  Bottom Layer w10: v1(1848.53,1811.6) 1852.62,1807.52 1925.82,1807.52 1944.9,1788.43 1944.9,1775.75 R56.1@1992.7,1727.94
NetC212_2: C212.2 R210.2 | length 51.3
  Top Layer w10: R210.2@2425,2041.84 2425.4,2042.24 C212.2@2476.1,2042.24
NetC214_1: C214.1 R214.1 | length 65
  Top Layer w30: C214.1@2713.98,2191.11 R214.1@2713.98,2256.11
NetC222_2: C222.2 R220.2 | length 49
  Top Layer w8: C222.2@2089.5,1314.38 2137.41,1314.38 R220.2@2138.2,1315.17
NetC224_1: C224.1 R224.1 | length 63.3
  Top Layer w10: R224.1@2092.84,946.61 R224.1@2094.45,945
  Top Layer w35: R224.1@2092.84,946.61 C224.1@2092.84,1007.66
NetC262_2: C262.2 R260.2 | length 46.6
  Top Layer w10: C262.2@2205,2012.92 2250.01,2012.92 R260.2@2251.12,2014.04
NetC264_1: C264.1 R264.1 | length 65
  Top Layer w40: C264.1@1703.19,2153.63 R264.1@1703.19,2218.63
NetC421_1: C421.1 Q420.1 Q420.2 Q420.3 R423.2 R424.2 R425.1 R429.2 | length 171.2
  Top Layer w10: R425.1@1506.38,575.04 1508.98,575.04 C421.1@1558.62,624.69
  Top Layer w20: C421.1@1558.62,624.69 1587.09,653.15 R424.2@1587.09,711.24
  other v2: 1589.7,695 1587.09,730
NetC451_1: C451.1 Q450.4 Q450.7 R453.2 R454.2 R455.1 | length 344.5
  Top Layer w8: R454.2@2825.17,985.03 R454.2@2846.94,963.26 ; R454.2@2855.36,963.26 R454.2@2846.94,963.26 ; R454.2@2859.81,976.13 R454.2@2846.94,963.26 ; C451.1@2925,893.62 2935,893.62 R455.1@2980,848.62
  Top Layer w25: R454.2@2855.36,963.26 C451.1@2925,893.62
  Top Layer w30: R454.2@2827.26,976.02 2827.26,1029.04 ; R454.2@2854.38,967.11 2854.38,1029.04
  other v1: 2827.26,957.24 2868.21,957.24
NetC461_1: C461.1 Q460.4 Q460.7 R463.2 R464.2 R465.1 | length 353.4
  Top Layer w10: R465.1@1516.38,2725 1516.38,2779.25 C461.1@1527.13,2790 1527.13,2845.48 R464.2@1552.2,2870.56
  Bottom Layer w10: R463.2@1559.37,2863.39 Q460.4@1649.11,2863.39 ; R463.2@1559.98,2862.78 1594.02,2828.74 Q460.7@1649.11,2828.74
  other v1: 1552.2,2855 1552.2,2885
NetC471_1: C471.1 Q470.4 Q470.7 R473.2 R475.1 | length 58.3
  Top Layer w25: R475.1@3310,2271.82 3311.81,2273.62 C471.1@3367.59,2273.62
NetC490_1: C490.1 J491.1 R490.2 U490.2 | length 353.5
  Top Layer w10: J491.1@436.25,2295.44 528.6,2295.44 C490.1@587.11,2353.94 ; R490.2@589.65,2290.44 587.11,2292.98 C490.1@587.11,2353.94 ; U490.2@666.46,2408.07 663.27,2404.89 663.27,2384.21 633,2353.94 C490.1@587.11,2353.94
NetC491_1: C491.1 J493.1 L410.2 R491.2 TP490.1 U490.6 | length 871.5
  Top Layer w10: R491.2@562.75,2568.15 562.75,2702.25 658.23,2702.25 699.68,2660.79 L410.2@699.68,2620.44 ; U490.6@686.14,2482.88 686.14,2497.72 ; TP490.1@847.17,2685.44 782.17,2620.44 L410.2@699.68,2620.44 ; J493.1@897.17,2525.44 893.71,2528.9 C491.1@776.14,2528.9 732.17,2528.9 707.48,2504.22 692.64,2504.22 686.14,2497.72 ; 686.14,2497.72 686.14,2606.89 L410.2@699.68,2620.44
NetC493_1: C493.1 J494.2 U491.6 | length 286.9
  Top Layer w10: J494.2@970,2145 1058.56,2056.44 1132.58,2056.44 1143.49,2045.54 ; U491.6@1143.49,2056.44 1143.49,2045.54 ; C493.1@1150.38,1987.03 1150.38,2010.74 1143.49,2017.63 1143.49,2045.54
NetD99_3: D99.3 J99.1 | length 134.7
  Top Layer w10: D99.3@1005.89,592.17 1013.77,592.17 1027.38,578.55 1076.1,578.55 J99.1@1117.74,536.91
NetJ421_1: J421.1 R421.1 | length 144.5
  Top Layer w10: J421.1@1475.28,960 1475.28,909.02 R421.1@1541.38,842.92
NetJ422_1: J422.1 R425.2 | length 67.9
  Top Layer w10: J422.1@1440,515.04 1459.13,534.17 R425.2@1459.13,575.04
NetJ423_1: J423.1 R426.1 | length 83
  Top Layer w10: J423.1@1665.04,475 1696.54,506.5 R426.1@1735,506.5
NetJ451_1: J451.1 R451.1 | length 127.6
  Top Layer w8: J451.1@2705,848.1 2705,966.38 R451.1@2711.61,972.99
NetJ452_1: J452.1 R455.2 | length 59.5
  Top Layer w8: R455.2@2980,801.38 3011.91,801.38 J452.1@3031.39,781.9
NetJ453_1: J453.1 R456.1 | length 61
  Top Layer w10: J453.1@3131.61,964.24 3137.98,970.62 R456.1@3190,970.62
NetJ461_1: J461.1 R461.1 | length 233.2
  Bottom Layer w10: J461.1@1330,2745 1522.75,2745 R461.1@1551.38,2773.63
NetJ462_1: J462.1 R465.2 | length 71.4
  Top Layer w10: J462.1@1535,2665.48 1535,2696.38 R465.2@1563.62,2725
NetJ463_1: J463.1 R466.1 | length 67.6
  Top Layer w10: J463.1@1610.04,2439.35 1643.19,2439.35 R466.1@1667.57,2414.97
NetJ471_1: J471.1 R471.1 | length 159
  Top Layer w10: J471.1@3455.33,2610 3455.33,2558.34 3511.18,2502.49 R471.1@3539.5,2502.49
NetJ472_1: J472.1 R475.2 | length 62.3
  Top Layer w25: J472.1@3250.19,2325 3256.13,2319.06 R475.2@3310,2319.06
NetJ473_1: J473.1 R476.1 | length 69.6
  Top Layer w25: R476.1@3185,2026.88 3185,2091.48 J473.1@3188.5,2094.99
NetJ492_2: J492.2 R491.1 U490.8 | length 441
  Top Layer w10: J492.2@300,2300 505.16,2505.16 R491.1@562.75,2505.16 585.04,2482.88 U490.8@646.77,2482.88
NetJ495_2: J495.2 R493.2 U491.4 | length 207.2
  Top Layer w10: J495.2@1095.38,2286.72 R493.2@1095.38,2177.03 1095.38,2141.74 1129.49,2107.63 U491.4@1143.49,2107.63
NetJ496_1: J496.1 U491.5 | length 517
  Top Layer w10: U491.5@1143.49,2082.03 1122.79,2082.03 1051.4,2153.43 1051.4,2304.94 1077.16,2330.7 1113.59,2330.7 1191.12,2253.18 1199.39,2253.18 J496.1@1236.87,2290.66
NetL230_1: L230.1 U50.10 | length 505.9
  Top Layer w10: 2295.26,1220.65 2295.26,1475 2304.52,1484.25 U50.10@2304.52,1516.85
  Top Layer w20: 2297.95,1219.89 L230.1@2443.54,1074.31
NetL240_1: L240.1 U50.25 | length 435.3
  Top Layer w8: U50.25@2432.47,1676.3 2524.75,1676.3 2530.76,1682.31 2574.64,1682.31 2579.9,1677.05
  Top Layer w10: 2579.9,1677.05 2580.18,1676.77 2647.91,1676.77 2648.38,1676.3 2733.54,1676.3
  Top Layer w20: 2733.54,1676.3 2790.67,1619.17
  Top Layer w30: 2790.67,1619.17 L240.1@2839.14,1619.17
NetL250_1: L250.1 U50.20 | length 487.4
  Top Layer w8: U50.20@2432.47,1597.56 2462.83,1597.56 2488.06,1572.33 2502.98,1572.33
  Top Layer w10: 2502.98,1572.33 2650.08,1572.33 ; 2650.13,1572.28 2650.08,1572.33 ; 2665,1572.33 2650.08,1572.33
  Top Layer w15: 2665,1572.33 L250.1@2666.38,1327.97
NetL410_1: L410.1 U490.7 | length 147.4
  Top Layer w10: L410.1@642.6,2620.44 666.46,2596.58 U490.7@666.46,2482.88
